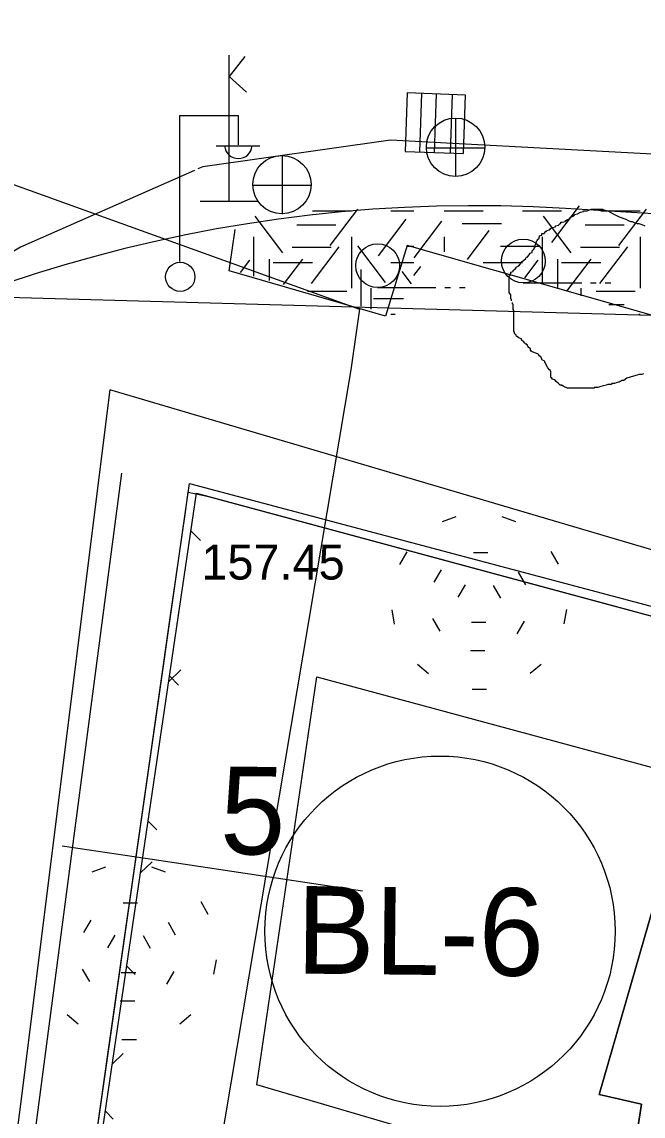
# Model space of a CAD drawing. Extents: x 419677 to 421689, y 4450851 to 4452923.
# Drawn here: x 420228.69 to 420249.96, y 4451941.04 to 4451978.52 of the extents above; entities that cross this region are included whole.
import ezdxf

# ---------------------------------------------------------------- set-up
doc = ezdxf.new("R2010")
doc.units = 0
for name, color, linetype in [('AA_HH', 7, 'Continuous'), ('Level 10', 7, 'Continuous'), ('Level 15', 7, 'Continuous'), ('Level 20', 7, 'Continuous'), ('Level 24', 7, 'Continuous'), ('Level 27', 7, 'Continuous'), ('Level 3', 7, 'Continuous'), ('Level 34', 7, 'Continuous'), ('Level 38', 7, 'Continuous'), ('Level 41', 7, 'Continuous'), ('Level 62', 7, 'Continuous'), ('Level 9', 7, 'Continuous'), ('MULKIYET SINIRI', 7, 'Continuous')]:
    doc.layers.add(name, color=color, linetype=linetype)

msp = doc.modelspace()

# ---------------------------------------------------------------- linework, layer by layer
at = {"layer": 'AA_HH'}
for p, q in [((420235.788, 4451972.375), (420235.788, 4451977.375)), ((420236.318, 4451977.332), (420235.788, 4451976.652)), ((420235.788, 4451976.652), (420236.38, 4451976.117)), ((420241.885, 4451976.084), (420241.815, 4451974.085)), ((420241.885, 4451976.084), (420241.815, 4451974.085)), ((420243.884, 4451976.014), (420241.885, 4451976.084)), ((420243.884, 4451976.014), (420241.885, 4451976.084)), ((420242.319, 4451974.068), (420242.389, 4451976.066)), ((420242.814, 4451974.05), (420242.884, 4451976.049)), ((420243.362, 4451974.031), (420243.432, 4451976.03)), ((420243.814, 4451974.015), (420243.884, 4451976.014)), ((420243.814, 4451974.015), (420243.884, 4451976.014)), ((420234.1, 4451970.31), (420234.1, 4451975.31)), ((420234.1, 4451975.31), (420236.1, 4451975.31)), ((420236.1, 4451974.31), (420236.1, 4451975.31)), ((420243.554, 4451973.218), (420243.554, 4451975.218)), ((420235.34, 4451974.27), (420236.84, 4451974.27)), ((420242.534, 4451974.208), (420244.534, 4451974.208)), ((420237.609, 4451971.935), (420237.609, 4451973.935)), ((420241.815, 4451974.085), (420243.814, 4451974.015)), ((420241.815, 4451974.085), (420243.814, 4451974.015)), ((420236.589, 4451972.925), (420238.589, 4451972.925)), ((420234.788, 4451972.375), (420236.788, 4451972.375)), ((420240.87, 4451969.421), (420242.87, 4451969.421)), ((420243.17, 4451969.421), (420243.37, 4451969.421)), ((420243.67, 4451969.421), (420243.87, 4451969.421)), ((420245.861, 4451969.576), (420247.861, 4451969.576)), ((420248.161, 4451969.576), (420248.361, 4451969.576)), ((420248.661, 4451969.576), (420248.861, 4451969.576))]:
    msp.add_line(p, q, dxfattribs=at)
for points in [[(420390.75, 4451923.523), (420355.577, 4451937.004), (420307.443, 4451957.787), (420280.515, 4451967.9), (420273.647, 4451970.301), (420269.934, 4451971.02), (420261.568, 4451972.752), (420253.278, 4451973.826), (420241.307, 4451974.471), (420234.881, 4451973.555), (420234.717, 4451973.483)], [(420234.596, 4451973.43), (420228.639, 4451970.8), (420223.376, 4451967.647), (420219.033, 4451964.362), (420211.265, 4451957.117), (420208.13, 4451953.689)], [(420234.596, 4451973.43), (420228.639, 4451970.8), (420223.376, 4451967.647), (420219.033, 4451964.362), (420211.265, 4451957.117), (420208.13, 4451953.689)], [(420258.708, 4451900.597), (420255.573, 4451901.639), (420225.478, 4451910.605), (420225.226, 4451910.854), (420229.238, 4451941.255), (420232.113, 4451963.06)]]:
    msp.add_lwpolyline(points, dxfattribs=at)
for points in [[(420253.07, 4451957.757), (420248.46, 4451941.78), (420249.914, 4451941.452), (420248.847, 4451934.599), (420231.114, 4451939.515), (420234.427, 4451962.705)], [(420253.07, 4451957.757), (420268.667, 4451952.723), (420262.187, 4451930.463), (420248.847, 4451934.599), (420249.914, 4451941.452), (420248.46, 4451941.78)]]:
    msp.add_lwpolyline(points, close=True, dxfattribs=at)
for centre, radius in [((420243.539, 4451974.226), 1), ((420237.594, 4451972.944), 1), ((420240.87, 4451970.171), 0.75), ((420245.861, 4451970.326), 0.75), ((420234.11, 4451969.786), 0.5)]:
    msp.add_circle(centre, radius, dxfattribs=at)
msp.add_arc((420236.1, 4451974.314), 0.474, 184.8384, 355.1464, dxfattribs=at)
at = {"layer": 'Level 10'}
msp.add_lwpolyline([(420320.676, 4451952.286), (420287.846, 4451965.918), (420283.914, 4451959.364), (420283.477, 4451950.626), (420231.702, 4451965.918)], dxfattribs=at)
at = {"layer": 'Level 15'}
for points in [[(420240.251, 4451968.677), (420239.949, 4451966.602), (420239.949, 4451966.602), (420231.732, 4451917.739), (420240.801, 4451915.152), (420236.082, 4451892.337), (420229.855, 4451894.289), (420220.346, 4451839.788), (420214.729, 4451827.789), (420207.555, 4451825.12), (420146.986, 4451843.868), (420162.882, 4451888.718), (420178.991, 4451939.954), (420183.444, 4451958.583), (420204.023, 4451977.132), (420216.413, 4451977.263), (420240.251, 4451968.677)], [(420414.132, 4451911.018), (420415.765, 4451915.419), (420282.101, 4451967.569), (420224.504, 4451969.178), (420220.055, 4451958.563), (420205.131, 4451843.779), (420215.712, 4451841.911), (420221.376, 4451877.395), (420222.223, 4451877.252)]]:
    msp.add_lwpolyline(points, dxfattribs=at)
at = {"layer": 'Level 20'}
for p, q in [((420233.154, 4451949.827), (420230.066, 4451950.289)), ((420233.154, 4451949.827), (420230.066, 4451950.289)), ((420240.356, 4451948.749), (420233.154, 4451949.827)), ((420240.356, 4451948.749), (420233.154, 4451949.827))]:
    msp.add_line(p, q, dxfattribs=at)
for points in [[(420236.733, 4451942.109), (420238.791, 4451956.081), (420251.808, 4451952.573), (420267.449, 4451948.101), (420281.49, 4451944.095)], [(420236.733, 4451942.109), (420238.791, 4451956.081), (420251.808, 4451952.573), (420267.449, 4451948.101), (420281.49, 4451944.095)], [(420281.49, 4451944.095), (420279.898, 4451934.306), (420279.164, 4451929.673), (420263.182, 4451934.359), (420249.755, 4451938.293), (420236.733, 4451942.109)], [(420281.49, 4451944.095), (420279.898, 4451934.306), (420279.164, 4451929.673), (420263.182, 4451934.359), (420249.755, 4451938.293), (420236.733, 4451942.109)]]:
    msp.add_lwpolyline(points, dxfattribs=at)
at = {"layer": 'Level 24'}
msp.add_circle((420243.008, 4451947.373), 6, dxfattribs=at)
msp.add_circle((420243.008, 4451947.373), 6, dxfattribs=at)
at = {"layer": 'Level 27'}
for points in [[(420231.124, 4451939.585), (420231.634, 4451943.154), (420233.025, 4451952.894), (420233.77, 4451958.11), (420234.276, 4451961.652), (420234.384, 4451962.408), (420235.029, 4451962.274)], [(420231.299, 4451939.533), (420231.802, 4451942.949), (420234.664, 4451962.372), (420235.029, 4451962.274)], [(420231.299, 4451939.533), (420231.802, 4451942.949), (420234.664, 4451962.372), (420235.029, 4451962.274)], [(420235.029, 4451962.274), (420248.61, 4451958.613)], [(420235.029, 4451962.274), (420248.61, 4451958.613)], [(420235.029, 4451962.274), (420248.61, 4451958.613)], [(420248.61, 4451958.613), (420253.146, 4451957.391), (420268.822, 4451952.909), (420285.985, 4451948.012), (420287.724, 4451962.476), (420333.69, 4451943.911), (420338.452, 4451942.062), (420340.782, 4451941.146)], [(420248.61, 4451958.613), (420253.146, 4451957.391), (420268.822, 4451952.909), (420285.985, 4451948.012), (420287.724, 4451962.476), (420333.69, 4451943.911), (420338.452, 4451942.062), (420340.782, 4451941.146)], [(420248.61, 4451958.613), (420253.146, 4451957.391), (420268.822, 4451952.909), (420285.985, 4451948.012), (420287.724, 4451962.476), (420333.69, 4451943.911), (420338.452, 4451942.062), (420340.782, 4451941.146)]]:
    msp.add_lwpolyline(points, dxfattribs=at)
at = {"layer": 'Level 3'}
for points in [[(420245.459, 4451968.96), (420245.459, 4451968.986), (420245.459, 4451969.011), (420245.433, 4451969.037), (420245.433, 4451969.063), (420245.433, 4451969.089), (420245.433, 4451969.115), (420245.433, 4451969.141), (420245.433, 4451969.167), (420245.381, 4451969.245), (420245.381, 4451969.323), (420245.381, 4451969.349), (420245.381, 4451969.427), (420245.381, 4451969.505), (420245.381, 4451969.531), (420245.381, 4451969.557), (420245.381, 4451969.583), (420245.381, 4451969.609), (420245.381, 4451969.635), (420245.381, 4451969.661), (420245.381, 4451969.687), (420245.381, 4451969.713), (420245.381, 4451969.739), (420245.381, 4451969.817), (420245.407, 4451969.842), (420245.407, 4451969.868), (420245.407, 4451969.894), (420245.433, 4451969.894), (420245.433, 4451969.92), (420245.433, 4451969.946), (420245.511, 4451969.972), (420245.511, 4451969.998), (420245.589, 4451970.076), (420245.641, 4451970.128), (420245.692, 4451970.154), (420245.692, 4451970.18), (420245.718, 4451970.18), (420245.77, 4451970.258), (420245.822, 4451970.31), (420245.874, 4451970.362), (420245.952, 4451970.414), (420245.952, 4451970.44), (420246.004, 4451970.466), (420246.004, 4451970.492), (420246.03, 4451970.492), (420246.082, 4451970.57), (420246.082, 4451970.596), (420246.159, 4451970.622), (420246.159, 4451970.647), (420246.159, 4451970.673), (420246.211, 4451970.725), (420246.237, 4451970.751), (420246.237, 4451970.777), (420246.263, 4451970.803), (420246.263, 4451970.829), (420246.263, 4451970.855), (420246.263, 4451970.881), (420246.289, 4451970.907), (420246.289, 4451970.933), (420246.289, 4451970.959), (420246.315, 4451970.959), (420246.315, 4451970.985), (420246.315, 4451971.011), (420246.341, 4451971.037), (420246.341, 4451971.063), (420246.393, 4451971.089), (420246.419, 4451971.167), (420246.419, 4451971.193), (420246.497, 4451971.219), (420246.497, 4451971.245), (420246.497, 4451971.271), (420246.574, 4451971.271), (420246.626, 4451971.323), (420246.626, 4451971.349), (420246.652, 4451971.349), (420246.678, 4451971.375), (420246.756, 4451971.401), (420246.782, 4451971.427), (420246.808, 4451971.427), (420246.808, 4451971.453), (420246.86, 4451971.478), (420246.964, 4451971.504), (420246.964, 4451971.53), (420247.067, 4451971.556), (420247.119, 4451971.608), (420247.145, 4451971.608), (420247.145, 4451971.634), (420247.145, 4451971.66), (420247.197, 4451971.66), (420247.301, 4451971.686), (420247.301, 4451971.712), (420247.327, 4451971.712), (420247.353, 4451971.712), (420247.353, 4451971.738), (420247.405, 4451971.764), (420247.431, 4451971.764), (420247.482, 4451971.816), (420247.56, 4451971.868), (420247.612, 4451971.894), (420247.612, 4451971.92), (420247.716, 4451971.946)], [(420247.716, 4451971.946), (420247.82, 4451971.998), (420247.923, 4451972.024), (420247.923, 4451972.05), (420247.949, 4451972.05), (420247.975, 4451972.05), (420248.053, 4451972.05), (420248.183, 4451972.102), (420248.287, 4451972.102), (420248.364, 4451972.102), (420248.416, 4451972.102), (420248.494, 4451972.102), (420248.546, 4451972.102), (420248.572, 4451972.102), (420248.624, 4451972.076), (420248.754, 4451972.05), (420248.935, 4451971.946), (420249.143, 4451971.842), (420249.376, 4451971.764), (420249.454, 4451971.712), (420249.532, 4451971.686), (420249.584, 4451971.686), (420249.636, 4451971.66), (420249.687, 4451971.634), (420249.713, 4451971.634), (420249.765, 4451971.608), (420249.817, 4451971.608), (420249.921, 4451971.582), (420250.025, 4451971.53)], [(420247.405, 4451965.973), (420247.379, 4451965.973), (420247.249, 4451966.025), (420247.223, 4451966.051), (420247.197, 4451966.051), (420247.197, 4451966.077), (420247.119, 4451966.077), (420247.067, 4451966.129), (420246.99, 4451966.207), (420246.938, 4451966.259), (420246.86, 4451966.285), (420246.834, 4451966.311), (420246.808, 4451966.337), (420246.808, 4451966.363), (420246.808, 4451966.441), (420246.808, 4451966.519), (420246.808, 4451966.544), (420246.782, 4451966.57), (420246.782, 4451966.596), (420246.756, 4451966.596), (420246.704, 4451966.674), (420246.652, 4451966.752), (420246.626, 4451966.83), (420246.6, 4451966.856), (420246.6, 4451966.882), (420246.574, 4451966.908), (420246.523, 4451966.934), (420246.497, 4451966.96), (420246.497, 4451966.986), (420246.471, 4451967.012), (420246.471, 4451967.038), (420246.393, 4451967.09), (420246.393, 4451967.116), (420246.367, 4451967.142), (420246.289, 4451967.168), (420246.237, 4451967.194), (420246.159, 4451967.22), (420246.133, 4451967.246), (420246.108, 4451967.272), (420246.108, 4451967.298), (420246.108, 4451967.324), (420246.03, 4451967.375), (420246.03, 4451967.401), (420246.004, 4451967.427), (420246.004, 4451967.453), (420245.978, 4451967.453), (420245.978, 4451967.479), (420245.952, 4451967.479), (420245.926, 4451967.505), (420245.9, 4451967.531), (420245.874, 4451967.557), (420245.848, 4451967.583), (420245.822, 4451967.609), (420245.796, 4451967.635), (420245.796, 4451967.661), (420245.744, 4451967.687), (420245.718, 4451967.687), (420245.692, 4451967.713), (420245.641, 4451967.739), (420245.615, 4451967.765), (420245.615, 4451967.791), (420245.589, 4451967.817), (420245.563, 4451967.843), (420245.563, 4451967.869), (420245.563, 4451967.895), (420245.537, 4451967.921), (420245.537, 4451967.947), (420245.537, 4451967.973), (420245.537, 4451968.051), (420245.537, 4451968.103), (420245.537, 4451968.129), (420245.537, 4451968.155), (420245.537, 4451968.18), (420245.537, 4451968.206), (420245.537, 4451968.232), (420245.537, 4451968.258), (420245.537, 4451968.284), (420245.537, 4451968.31), (420245.537, 4451968.336), (420245.537, 4451968.362), (420245.537, 4451968.388), (420245.537, 4451968.414), (420245.537, 4451968.44), (420245.537, 4451968.466), (420245.537, 4451968.492), (420245.537, 4451968.518), (420245.537, 4451968.596), (420245.537, 4451968.622), (420245.537, 4451968.648), (420245.511, 4451968.648), (420245.511, 4451968.674), (420245.511, 4451968.7), (420245.511, 4451968.726), (420245.511, 4451968.752), (420245.511, 4451968.778), (420245.511, 4451968.804), (420245.511, 4451968.83), (420245.511, 4451968.856), (420245.485, 4451968.856), (420245.485, 4451968.882), (420245.485, 4451968.908)], [(420249.973, 4451966.467), (420249.921, 4451966.441), (420249.843, 4451966.441), (420249.817, 4451966.441), (420249.765, 4451966.415), (420249.636, 4451966.389), (420249.402, 4451966.311), (420249.298, 4451966.233), (420249.22, 4451966.233), (420249.195, 4451966.207), (420249.169, 4451966.207), (420249.143, 4451966.181), (420249.117, 4451966.181), (420249.039, 4451966.155), (420248.987, 4451966.129), (420248.961, 4451966.129), (420248.935, 4451966.129), (420248.909, 4451966.129), (420248.883, 4451966.129), (420248.883, 4451966.103), (420248.857, 4451966.103), (420248.831, 4451966.103), (420248.754, 4451966.103), (420248.702, 4451966.077), (420248.598, 4451966.051), (420248.52, 4451966.025), (420248.416, 4451965.999), (420248.364, 4451965.999), (420248.338, 4451965.999), (420248.313, 4451965.999), (420248.287, 4451965.999), (420248.287, 4451965.973), (420248.261, 4451965.973), (420248.235, 4451965.973), (420248.209, 4451965.973), (420248.183, 4451965.973), (420248.157, 4451965.973), (420248.131, 4451965.973), (420248.105, 4451965.973), (420248.079, 4451965.973), (420248.053, 4451965.973), (420247.975, 4451965.973), (420247.923, 4451965.973), (420247.846, 4451965.973), (420247.794, 4451965.973), (420247.768, 4451965.973), (420247.742, 4451965.973), (420247.69, 4451965.973), (420247.612, 4451965.973), (420247.586, 4451965.973), (420247.534, 4451965.973), (420247.508, 4451965.973), (420247.456, 4451965.973), (420247.431, 4451965.973), (420247.405, 4451965.973)]]:
    msp.add_lwpolyline(points, dxfattribs=at)
at = {"layer": 'Level 34'}
for p, q in [((420234.8, 4451960.752), (420234.474, 4451961.084)), ((420234.8, 4451960.752), (420234.474, 4451961.084)), ((420233.712, 4451955.913), (420234.133, 4451956.325)), ((420233.712, 4451955.913), (420234.133, 4451956.325)), ((420234.053, 4451955.798), (420233.742, 4451956.116)), ((420234.053, 4451955.798), (420233.742, 4451956.116)), ((420234.053, 4451955.798), (420234.053, 4451955.798)), ((420234.053, 4451955.798), (420234.053, 4451955.798)), ((420233.307, 4451950.845), (420233.01, 4451951.148)), ((420233.307, 4451950.845), (420233.01, 4451951.148)), ((420233.307, 4451950.845), (420233.307, 4451950.845)), ((420233.307, 4451950.845), (420233.307, 4451950.845)), ((420232.748, 4451949.368), (420233.143, 4451949.755)), ((420232.748, 4451949.368), (420233.143, 4451949.755)), ((420232.561, 4451945.89), (420232.278, 4451946.179)), ((420232.561, 4451945.89), (420232.278, 4451946.179)), ((420231.784, 4451942.824), (420232.154, 4451943.186)), ((420231.784, 4451942.824), (420232.154, 4451943.186)), ((420231.815, 4451940.936), (420231.546, 4451941.211)), ((420231.815, 4451940.936), (420231.546, 4451941.211))]:
    msp.add_line(p, q, dxfattribs=at)
at = {"layer": 'Level 38'}
for p, q in [((420243.548, 4451961.562), (420243.082, 4451961.392)), ((420243.548, 4451961.562), (420243.082, 4451961.392)), ((420245.601, 4451961.397), (420245.134, 4451961.566)), ((420245.601, 4451961.397), (420245.134, 4451961.566)), ((420241.87, 4451960.369), (420241.622, 4451959.939)), ((420241.87, 4451960.369), (420241.622, 4451959.939)), ((420244.645, 4451960.336), (420244.149, 4451960.336)), ((420244.645, 4451960.336), (420244.149, 4451960.336)), ((420247.067, 4451959.951), (420246.819, 4451960.381)), ((420247.067, 4451959.951), (420246.819, 4451960.381)), ((420243.045, 4451959.755), (420242.797, 4451959.326)), ((420243.045, 4451959.755), (420242.797, 4451959.326)), ((420245.948, 4451959.241), (420245.7, 4451959.67)), ((420245.948, 4451959.241), (420245.7, 4451959.67)), ((420243.868, 4451959.239), (420243.62, 4451958.81)), ((420243.868, 4451959.239), (420243.62, 4451958.81)), ((420245.09, 4451958.786), (420244.842, 4451959.215)), ((420245.09, 4451958.786), (420244.842, 4451959.215)), ((420247.261, 4451957.902), (420247.347, 4451958.39)), ((420247.261, 4451957.902), (420247.347, 4451958.39)), ((420241.352, 4451958.376), (420241.438, 4451957.888)), ((420241.352, 4451958.376), (420241.438, 4451957.888)), ((420242.748, 4451958.079), (420242.996, 4451957.65)), ((420242.748, 4451958.079), (420242.996, 4451957.65)), ((420244.086, 4451957.955), (420244.582, 4451957.955)), ((420244.086, 4451957.955), (420244.582, 4451957.955)), ((420245.651, 4451957.565), (420245.899, 4451957.994)), ((420245.651, 4451957.565), (420245.899, 4451957.994)), ((420244.051, 4451956.984), (420244.547, 4451956.984)), ((420244.051, 4451956.984), (420244.547, 4451956.984)), ((420242.235, 4451956.517), (420242.615, 4451956.198)), ((420242.235, 4451956.517), (420242.615, 4451956.198)), ((420246.092, 4451956.207), (420246.472, 4451956.526)), ((420246.092, 4451956.207), (420246.472, 4451956.526)), ((420244.107, 4451955.66), (420244.603, 4451955.66)), ((420244.107, 4451955.66), (420244.603, 4451955.66)), ((420231.552, 4451949.562), (420231.086, 4451949.392)), ((420231.552, 4451949.562), (420231.086, 4451949.392)), ((420233.605, 4451949.397), (420233.138, 4451949.566)), ((420233.605, 4451949.397), (420233.138, 4451949.566)), ((420232.649, 4451948.336), (420232.153, 4451948.336)), ((420232.649, 4451948.336), (420232.153, 4451948.336)), ((420235.071, 4451947.951), (420234.823, 4451948.381)), ((420235.071, 4451947.951), (420234.823, 4451948.381)), ((420231.014, 4451947.695), (420230.801, 4451947.326)), ((420231.014, 4451947.695), (420230.801, 4451947.326)), ((420231.049, 4451947.755), (420231.014, 4451947.696)), ((420231.049, 4451947.755), (420231.014, 4451947.696)), ((420231.014, 4451947.696), (420231.014, 4451947.696)), ((420231.014, 4451947.696), (420231.014, 4451947.696)), ((420233.952, 4451947.241), (420233.704, 4451947.67)), ((420233.952, 4451947.241), (420233.704, 4451947.67)), ((420231.872, 4451947.239), (420231.624, 4451946.81)), ((420231.872, 4451947.239), (420231.624, 4451946.81)), ((420233.094, 4451946.786), (420232.846, 4451947.215)), ((420233.094, 4451946.786), (420232.846, 4451947.215)), ((420230.752, 4451946.079), (420231, 4451945.65)), ((420230.752, 4451946.079), (420231, 4451945.65)), ((420235.265, 4451945.902), (420235.351, 4451946.39)), ((420235.265, 4451945.902), (420235.351, 4451946.39)), ((420232.09, 4451945.955), (420232.586, 4451945.955)), ((420232.09, 4451945.955), (420232.586, 4451945.955)), ((420233.655, 4451945.565), (420233.903, 4451945.994)), ((420233.655, 4451945.565), (420233.903, 4451945.994)), ((420232.055, 4451944.984), (420232.551, 4451944.984)), ((420232.055, 4451944.984), (420232.551, 4451944.984)), ((420230.239, 4451944.517), (420230.619, 4451944.198)), ((420230.239, 4451944.517), (420230.619, 4451944.198)), ((420234.096, 4451944.207), (420234.476, 4451944.526)), ((420234.096, 4451944.207), (420234.476, 4451944.526)), ((420232.111, 4451943.66), (420232.607, 4451943.66)), ((420232.111, 4451943.66), (420232.607, 4451943.66))]:
    msp.add_line(p, q, dxfattribs=at)
at = {"layer": 'Level 41'}
for p, q in [((420238.638, 4451972.043), (420239.981, 4451972.043)), ((420239.248, 4451970.859), (420240.197, 4451972.109)), ((420241.324, 4451972.043), (420242.112, 4451972.043)), ((420243.145, 4451972.043), (420244.488, 4451972.043)), ((420245.831, 4451972.043), (420247.174, 4451972.043)), ((420246.836, 4451970.964), (420247.787, 4451972.213)), ((420248.517, 4451972.043), (420249.86, 4451972.043)), ((420249.127, 4451970.859), (420250.076, 4451972.109)), ((420237.623, 4451970.614), (420236.673, 4451971.863)), ((420238.098, 4451971.573), (420239.441, 4451971.573)), ((420240.899, 4451970.508), (420241.849, 4451971.757)), ((420242.122, 4451970.439), (420243.071, 4451971.688)), ((420243.769, 4451971.609), (420245.112, 4451971.609)), ((420247.502, 4451970.614), (420246.552, 4451971.863)), ((420247.977, 4451971.573), (420249.32, 4451971.573)), ((420236.624, 4451971.16), (420236.624, 4451969.809)), ((420239.981, 4451971.16), (420239.981, 4451969.393)), ((420243.145, 4451971.16), (420243.145, 4451970.64)), ((420243.946, 4451970.385), (420244.696, 4451971.372)), ((420246.503, 4451971.16), (420246.503, 4451969.569)), ((420249.86, 4451971.16), (420249.86, 4451969.393)), ((420237.938, 4451970.803), (420239.281, 4451970.803)), ((420238.608, 4451969.562), (420239.558, 4451970.812)), ((420241.138, 4451969.596), (420240.189, 4451970.845)), ((420241.908, 4451970.836), (420242.112, 4451970.836)), ((420245.075, 4451970.836), (420246.418, 4451970.836)), ((420247.817, 4451970.803), (420249.16, 4451970.803)), ((420248.487, 4451969.562), (420249.437, 4451970.812)), ((420237.156, 4451970.388), (420237.156, 4451969.66)), ((420237.645, 4451969.523), (420238.305, 4451970.391)), ((420247.035, 4451970.388), (420247.035, 4451969.399)), ((420247.353, 4451969.297), (420248.184, 4451970.391)), ((420236.175, 4451969.935), (420236.495, 4451970.356)), ((420237.295, 4451970.276), (420238.638, 4451970.276)), ((420240.299, 4451970.038), (420240.299, 4451968.778)), ((420241.324, 4451970.276), (420242.112, 4451970.276)), ((420242.112, 4451969.83), (420242.35, 4451970.144)), ((420244.488, 4451970.276), (420245.831, 4451970.276)), ((420245.918, 4451969.756), (420246.374, 4451970.356)), ((420247.174, 4451970.276), (420248.517, 4451970.276)), ((420242.028, 4451969.546), (420241.706, 4451969.97)), ((420238.472, 4451969.295), (420239.815, 4451969.295)), ((420240.653, 4451968.678), (420240.653, 4451969.393)), ((420247.846, 4451969.14), (420247.846, 4451969.393)), ((420248.351, 4451969.295), (420249.694, 4451969.295)), ((420240.735, 4451969.05), (420241.761, 4451969.05)), ((420241.324, 4451968.509), (420241.47, 4451968.509)), ((420248.789, 4451968.839), (420249.32, 4451968.839)), ((420249.823, 4451968.509), (420249.86, 4451968.509))]:
    msp.add_line(p, q, dxfattribs=at)
at = {"layer": 'Level 62'}
for p, q in [((420241.885, 4451970.865), (420241.144, 4451968.44)), ((420251.432, 4451968.131), (420241.885, 4451970.865)), ((420241.144, 4451968.44), (420235.787, 4451969.994))]:
    msp.add_line(p, q, dxfattribs=at)
for points in [[(420255.213, 4451971.65), (420247.303, 4451972.13)], [(420235.787, 4451969.994), (420235.995, 4451971.408)]]:
    msp.add_lwpolyline(points, dxfattribs=at)
msp.add_arc((420244.27, 4451922.223), 50, 86.5224, 164.9279, dxfattribs=at)
for points, degree in [([(420301.269, 4451982.918), (420289.191, 4451973.63), (420250.246, 4451985.779), (420242.55, 4451988.153), (420241.405, 4451988.503)], 3), ([(420174.141, 4451957.431), (420207.126, 4451990.277), (420233.269, 4451982.965), (420233.274, 4451982.982)], 2)]:
    msp.add_open_spline(points, degree=degree, dxfattribs=at)
at = {"layer": 'Level 9'}
msp.add_lwpolyline([(420425.574, 4451910.283), (420391.286, 4451924.082), (420343.881, 4451942.651), (420287.846, 4451965.918), (420283.914, 4451959.364), (420283.477, 4451950.626), (420231.702, 4451965.918), (420228.644, 4451941.45), (420224.602, 4451910.32), (420222.636, 4451894.154), (420216.956, 4451865.1), (420209.201, 4451819.114), (420204.832, 4451797.924), (420203.303, 4451783.287), (420202.429, 4451776.297), (420195.86, 4451755.756)], dxfattribs=at)
msp.add_lwpolyline([(420425.574, 4451910.283), (420391.286, 4451924.082), (420343.881, 4451942.651), (420287.846, 4451965.918), (420283.914, 4451959.364), (420283.477, 4451950.626), (420231.702, 4451965.918), (420228.644, 4451941.45), (420224.602, 4451910.32), (420222.636, 4451894.154), (420216.956, 4451865.1), (420209.201, 4451819.114), (420204.832, 4451797.924), (420203.303, 4451783.287), (420202.429, 4451776.297), (420195.86, 4451755.756)], dxfattribs=at)
at = {"layer": 'MULKIYET SINIRI'}
msp.add_lwpolyline([(420231.299, 4451939.533), (420231.802, 4451942.949), (420234.664, 4451962.372), (420253.146, 4451957.391), (420268.822, 4451952.909), (420285.985, 4451948.012), (420285.171, 4451941.809), (420284.013, 4451934.694), (420283.847, 4451933.672), (420282.403, 4451924.555), (420262.057, 4451930.52), (420261.333, 4451930.733), (420261.084, 4451930.806), (420248.63, 4451934.454)], close=True, dxfattribs=at)
msp.add_lwpolyline([(420231.299, 4451939.533), (420231.802, 4451942.949), (420234.664, 4451962.372), (420253.146, 4451957.391), (420268.822, 4451952.909), (420285.985, 4451948.012), (420285.171, 4451941.809), (420284.013, 4451934.694), (420283.847, 4451933.672), (420282.403, 4451924.555), (420262.057, 4451930.52), (420261.333, 4451930.733), (420261.084, 4451930.806), (420248.63, 4451934.454)], close=True, dxfattribs=at)

# ---------------------------------------------------------------- texts
at = {"layer": 'AA_HH'}
msp.add_text('157.45 ', height=1.2, dxfattribs=at).set_placement((420234.833, 4451959.419))
at = {"layer": 'Level 20'}
msp.add_text('5', height=3, rotation=359.4141, dxfattribs=at).set_placement((420235.465, 4451950.017))
msp.add_text('5', height=3, rotation=359.4141, dxfattribs=at).set_placement((420235.465, 4451950.017))
at = {"layer": 'Level 24'}
msp.add_text('BL-6', height=3, rotation=359.4141, dxfattribs=at).set_placement((420238.079, 4451945.924))
msp.add_text('BL-6', height=3, rotation=359.4141, dxfattribs=at).set_placement((420238.079, 4451945.924))

doc.saveas('drawing.dxf')
